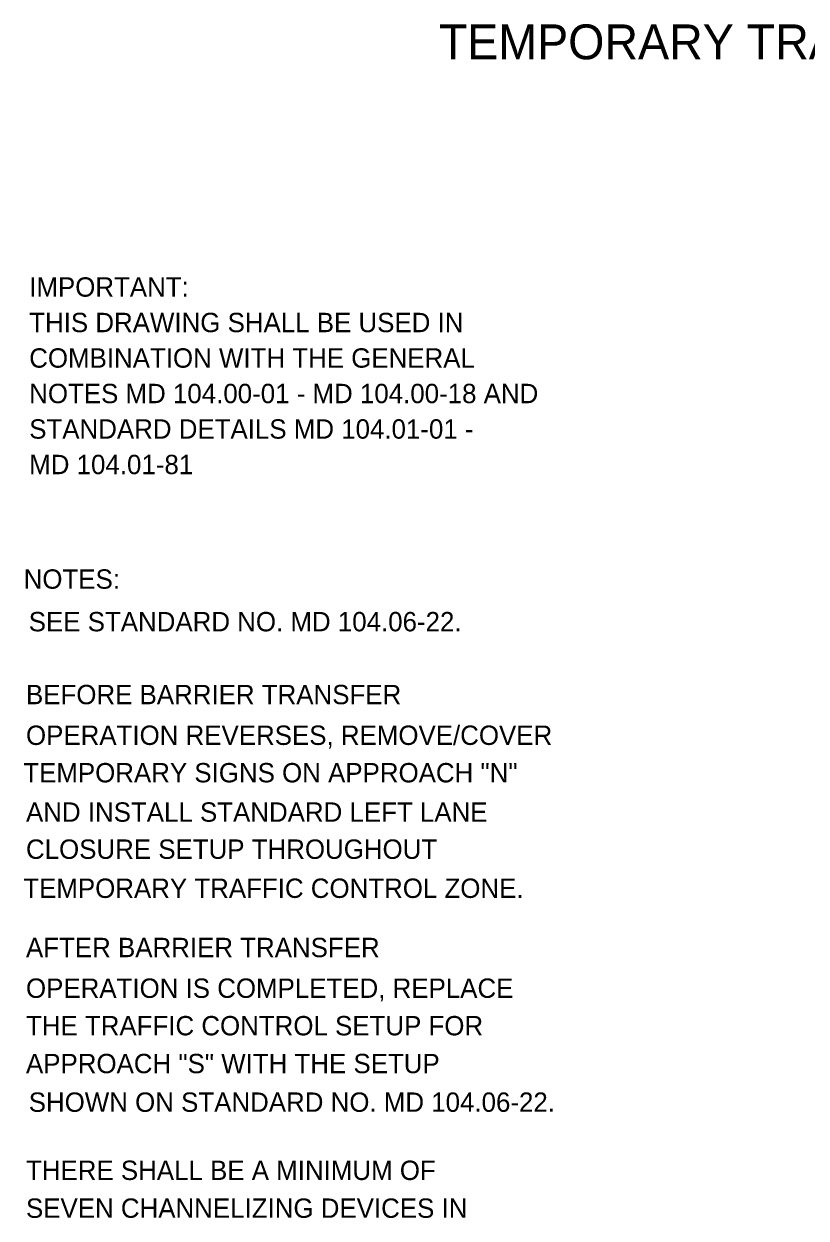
# Model space of a CAD drawing. Extents: x 1531.5 to 1538.6, y 1529.6 to 1539.6.
# Drawn here: x 1531.456 to 1533.881, y 1535.896 to 1539.597 of the extents above; entities that cross this region are included whole.
import ezdxf

# ---------------------------------------------------------------- set-up
doc = ezdxf.new("R2010")
doc.units = 0
doc.layers.add('DETL-NOTE', color=7, linetype='Continuous')
doc.layers.add('DETL-TITL', color=7, linetype='Continuous')

msp = doc.modelspace()

# ---------------------------------------------------------------- texts
at = {"layer": 'DETL-NOTE'}
for s, p in [('IMPORTANT:', (1531.4724, 1538.7517)), ('THIS DRAWING SHALL BE USED IN', (1531.4724, 1538.6417)), ('COMBINATION WITH THE GENERAL', (1531.4724, 1538.5317)), ('NOTES MD 104.00-01 - MD 104.00-18 AND', (1531.4724, 1538.4217)), ('STANDARD DETAILS MD 104.01-01 -', (1531.4724, 1538.3117)), ('MD 104.01-81', (1531.4724, 1538.2017)), ('NOTES:', (1531.4552, 1537.8467)), ('SEE STANDARD NO. MD 104.06-22.', (1531.4709, 1537.7147)), ('BEFORE BARRIER TRANSFER', (1531.4624, 1537.4888)), ('OPERATION REVERSES, REMOVE/COVER', (1531.4624, 1537.3627)), ('TEMPORARY SIGNS ON APPROACH "N"', (1531.454, 1537.2466)), ('AND INSTALL STANDARD LEFT LANE', (1531.4624, 1537.1247)), ('CLOSURE SETUP THROUGHOUT ', (1531.4624, 1537.0097)), ('TEMPORARY TRAFFIC CONTROL ZONE.', (1531.454, 1536.8886)), ('AFTER BARRIER TRANSFER ', (1531.4624, 1536.705)), ('OPERATION IS COMPLETED, REPLACE', (1531.4624, 1536.5789)), ('THE TRAFFIC CONTROL SETUP FOR', (1531.4624, 1536.4627)), ('APPROACH "S" WITH THE SETUP', (1531.4624, 1536.3454)), ('SHOWN ON STANDARD NO. MD 104.06-22.', (1531.4709, 1536.2258)), ('THERE SHALL BE A MINIMUM OF', (1531.4624, 1536.0146)), ('SEVEN CHANNELIZING DEVICES IN ', (1531.4624, 1535.8973))]:
    msp.add_text(s, height=0.06, dxfattribs=at).set_placement(p)
at = {"layer": 'DETL-TITL'}
msp.add_text('TEMPORARY TRAFFIC CONTROL TYPICAL APPLICATION', height=0.108, dxfattribs=at).set_placement((1532.7424, 1539.4874))

doc.saveas('drawing.dxf')
